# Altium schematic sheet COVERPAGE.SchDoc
size 420 x 297 mm
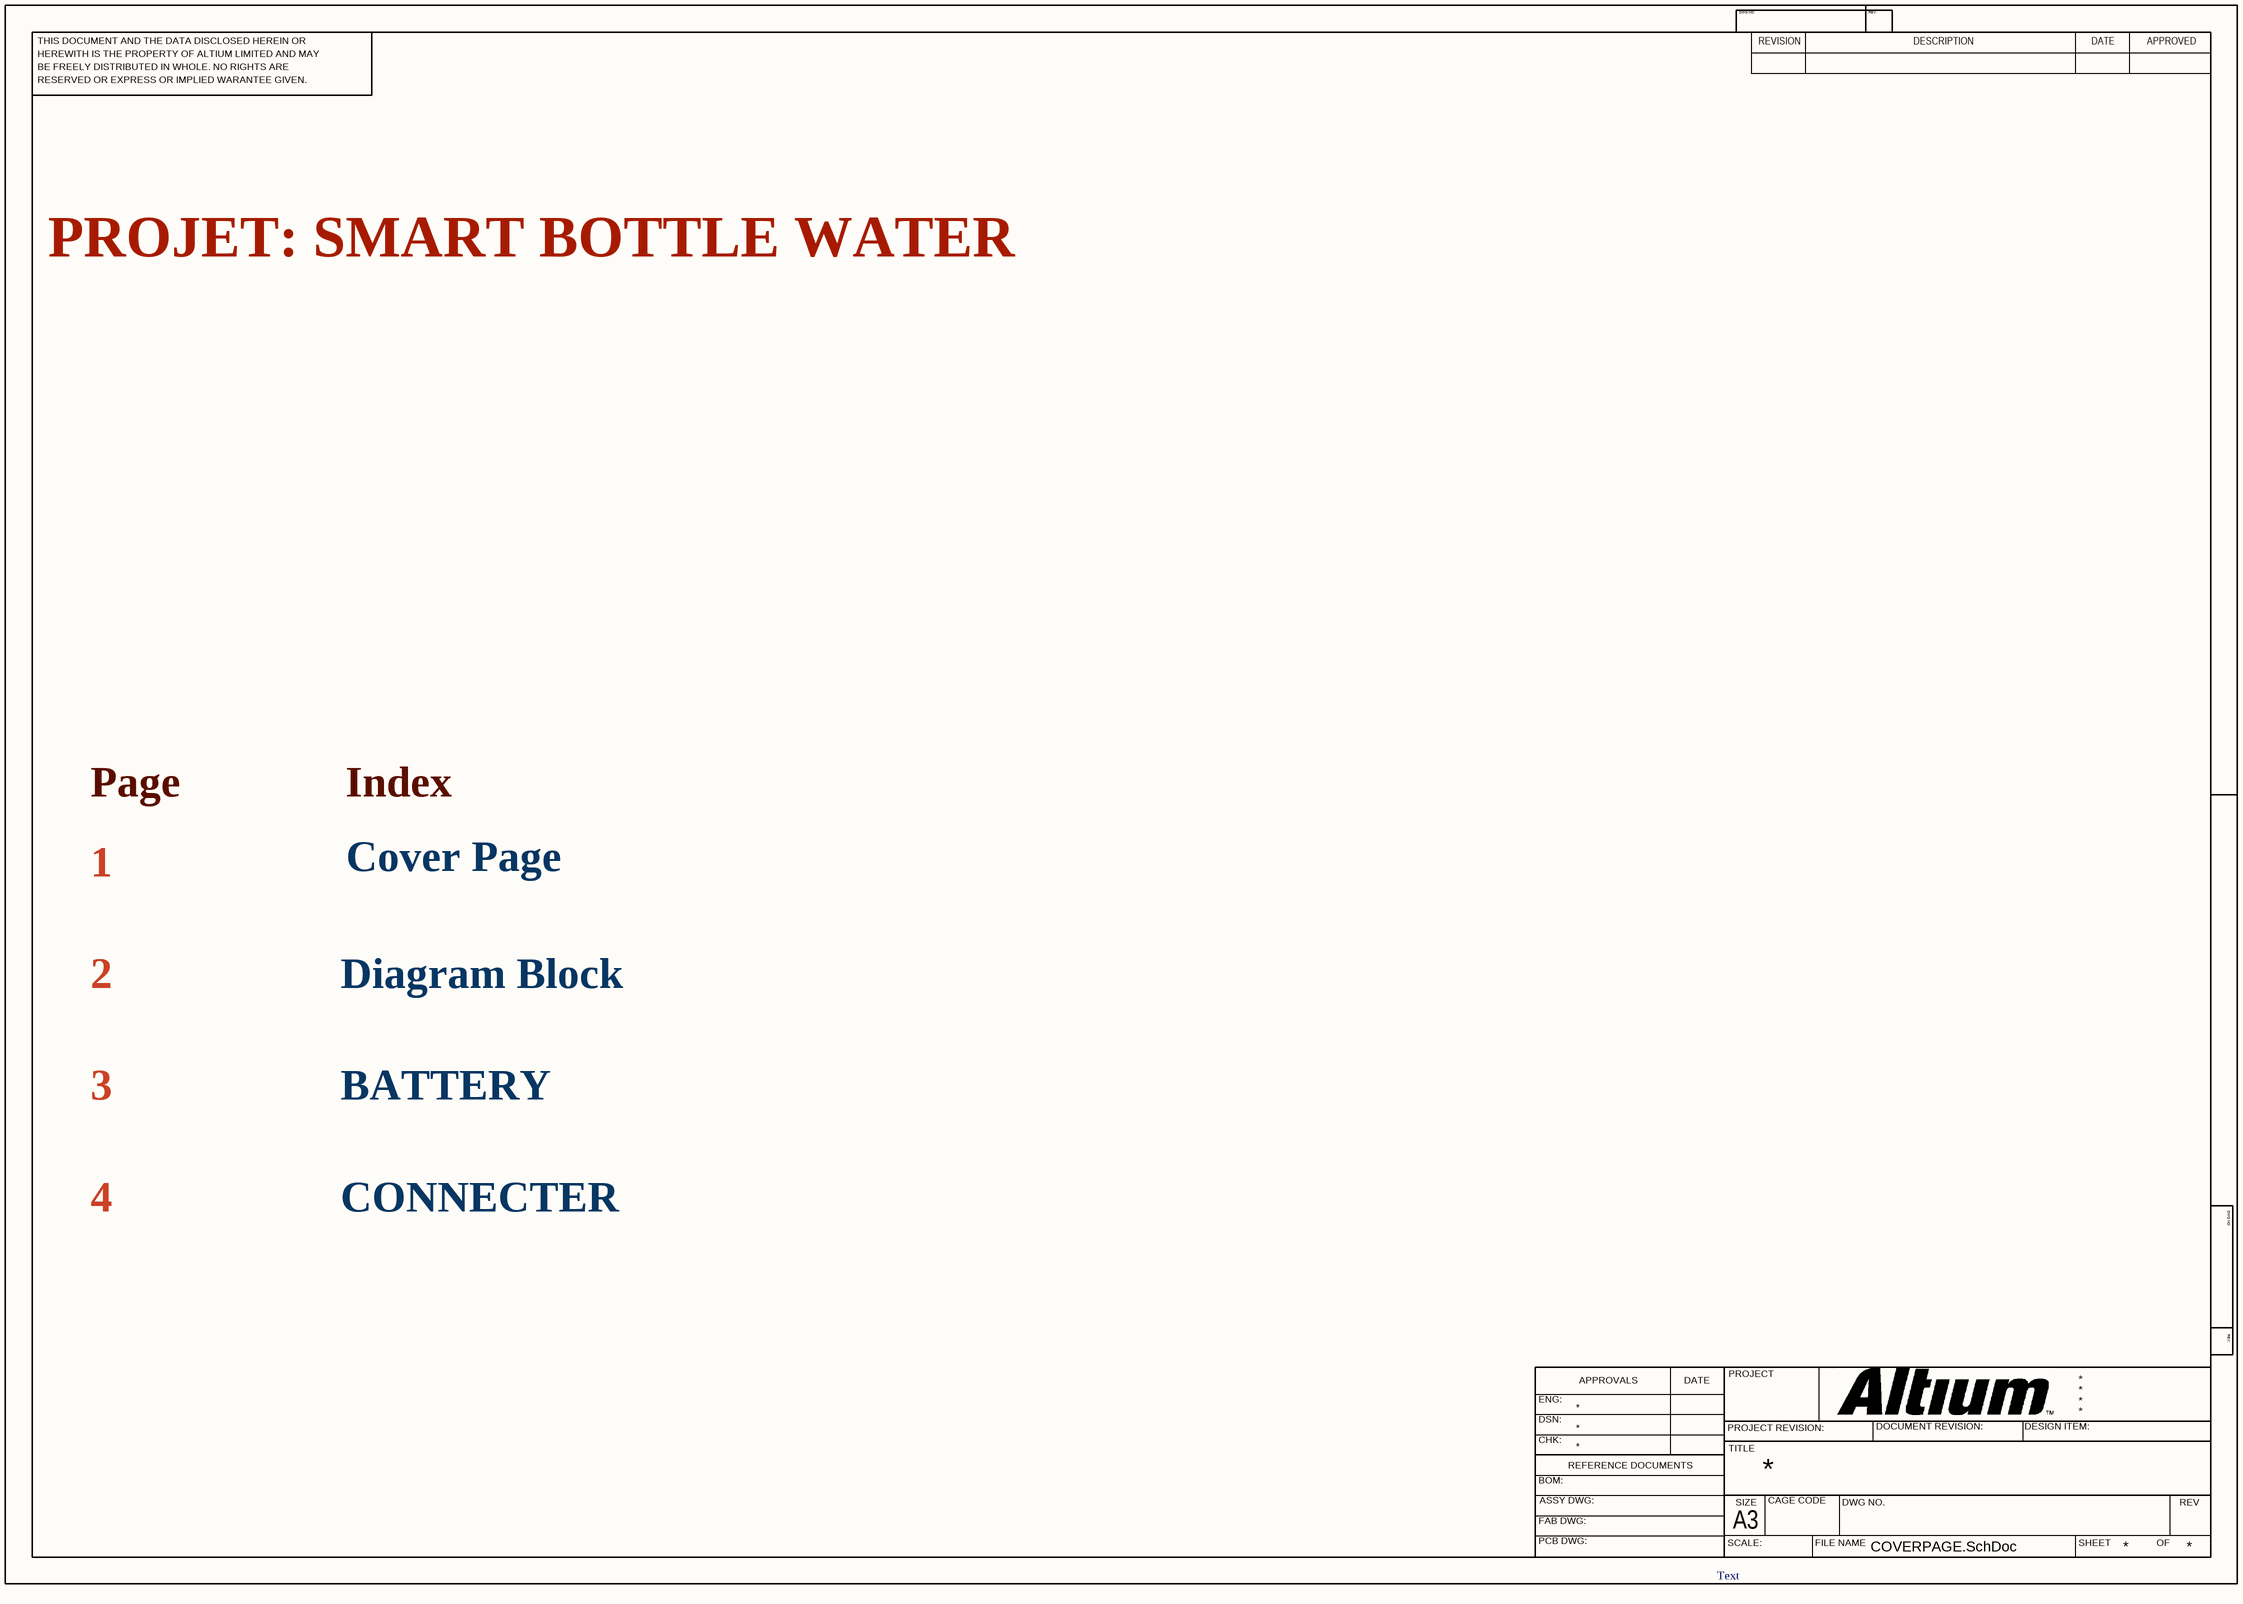
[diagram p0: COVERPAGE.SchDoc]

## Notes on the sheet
- PROJET: SMART BOTTLE WATER
- Page               Index
- 1
- Cover Page
- 2
- Diagram Block
- 3
- BATTERY
- 4
- CONNECTER
- Text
